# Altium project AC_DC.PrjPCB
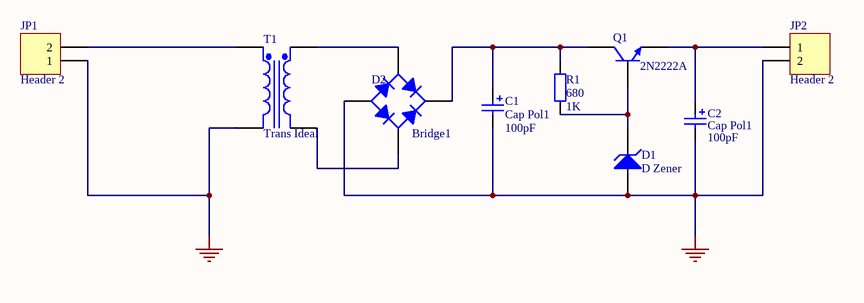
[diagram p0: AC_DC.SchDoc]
1 sheet, 9 parts. Net scope: global (net labels, ports and power ports of the same name join across sheets).
Board file: AC_DC.PCBDOC

## Sheet AC_DC.SchDoc
size B

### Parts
C1  Cap Pol1  value 100pF  [RB7.6-15]
C2  Cap Pol1  value 100pF  [RB7.6-15]
D1  D Zener  [DIODE-0.7]
D2  Bridge1  [E-BIP-P4/D10]
JP1  Header 2  [HDR1X2]
JP2  Header 2  [HDR1X2]
Q1  2N2222A  [CAN-3/D5.8]
R1  680  value 1K  [AXIAL-0.4]
T1  Trans Ideal  [TRF_4]

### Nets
GND: C1.2 C2.2 D1.1(A) D2.1(A) JP1.1 JP2.2 T1.2(Pri-)
NetC1_1: C1.1 D2.3(K) Q1.2(C) R1.2
NetC2_1: C2.1 JP2.1 Q1.3(E)
NetD1_2: D1.2(K) Q1.1(B) R1.1
NetD2_2: D2.2(C) T1.3(Sec+)
NetD2_4: D2.4(C) T1.4(Sec-)
NetJP1_2: JP1.2 T1.1(Pri+)

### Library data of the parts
C1 C2 = Cap Pol1: Polarized Capacitor (Radial); Manufacturer: Generic Components; Class I: Passive
D1 = D Zener: Zener Diode; Manufacturer: Generic Components; Class I: Discrete; Class II: Diode - Zener
D2 = Bridge1: Full Wave Diode Bridge; Manufacturer: Generic Components; Class I: Discrete; Class II: Rectifier - Bridge
JP1 JP2 = Header 2: Header, 2-Pin; Manufacturer: Generic Components; Class I: Connector
Q1 = 2N2222A: High Speed Switches; Manufacturer: ST-Microelectronics; Revision 1: 17-Jul-2002: Re-released for DXP Platform.; Revision 2: 11-Dec-2002: Sim Port Map correction; Class I: Discrete; Class II: BJT - Low Power
R1 = Res2: Resistor; Manufacturer: Generic Components; Class I: Passive
T1 = Trans Ideal: Transformer (Ideal); Manufacturer: Generic Components; Class I: Passive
